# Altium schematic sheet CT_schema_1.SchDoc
size 391 x 258 mm
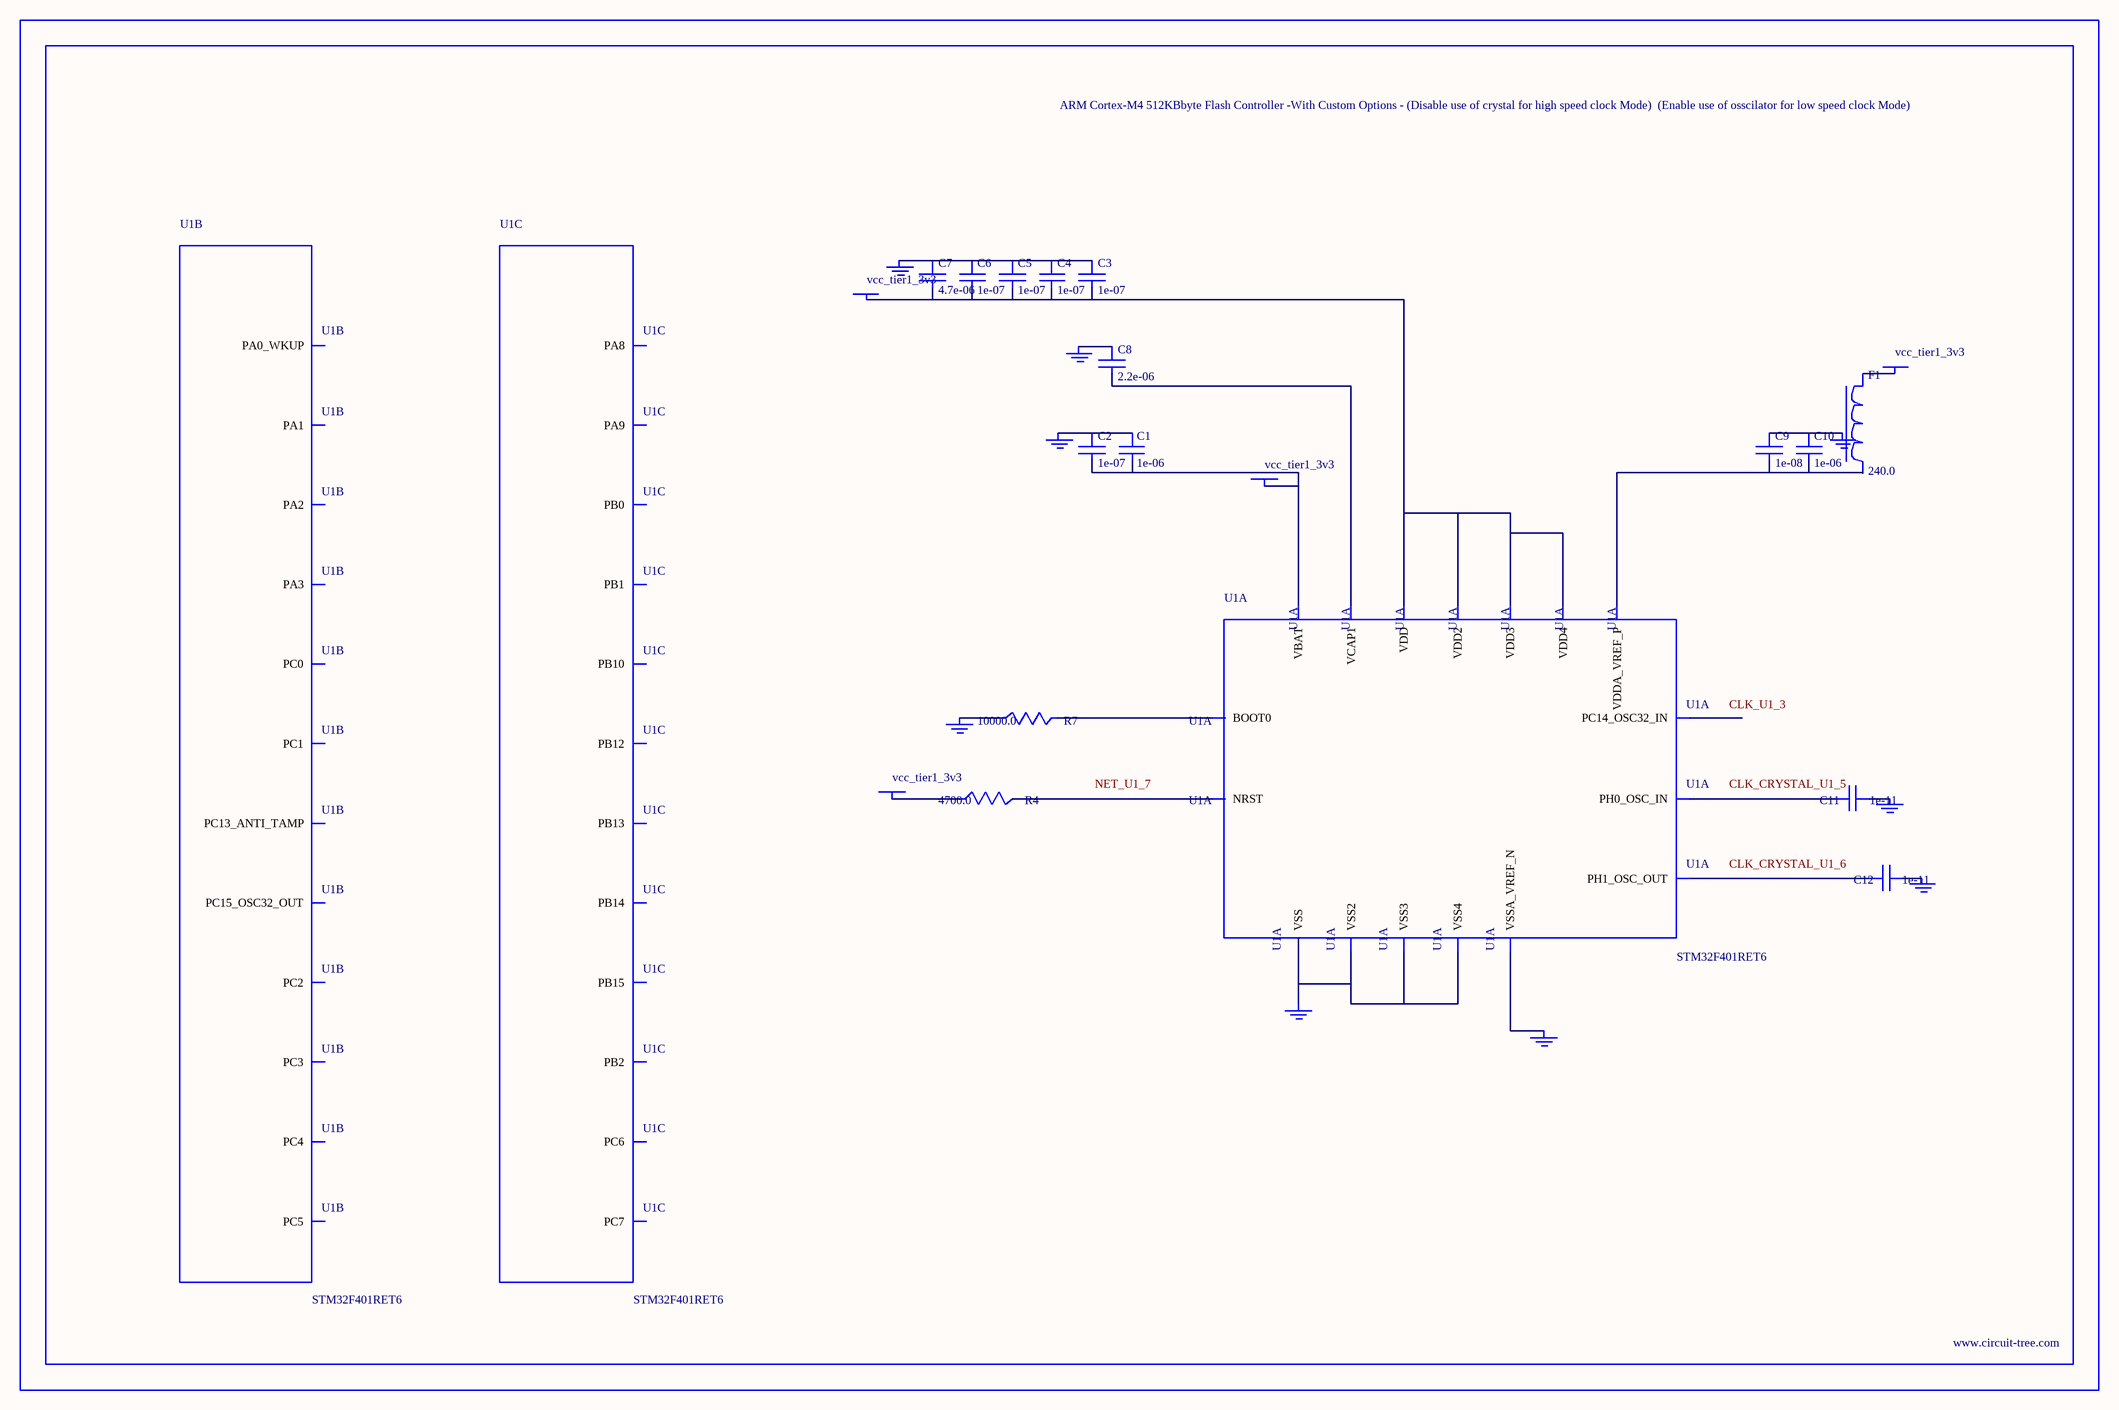
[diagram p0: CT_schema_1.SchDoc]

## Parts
BORDER0  (no value)
C1  1e-06  [C0603]
C2  1e-07  [C0603]
C3  1e-07  [C0603]
C4  1e-07  [C0603]
C5  1e-07  [C0603]
C6  1e-07  [C0603]
C7  4.7e-06  [C0603]
C8  2.2e-06  [C0603]
C9  1e-08  [C0603]
C10  1e-06  [C0603]
C11  1e-11  [C0402]
C12  1e-11  [C0402]
F1  240.0  [L0603]
GND_INSTANCE_0_0  (no value)
GND_INSTANCE_0_1  (no value)
GND_INSTANCE_0_2  (no value)
GND_INSTANCE_0_3  (no value)
GND_INSTANCE_0_4  (no value)
GND_INSTANCE_0_5  (no value)
GND_INSTANCE_0_6  (no value)
GND_INSTANCE_0_7  (no value)
GND_INSTANCE_0_8  (no value)
POWER_INSTANCE_0_0  vcc_tier1_3v3
POWER_INSTANCE_0_1  vcc_tier1_3v3
POWER_INSTANCE_0_2  vcc_tier1_3v3
POWER_INSTANCE_0_3  vcc_tier1_3v3
R4  4700.0  [R0603]
R7  10000.0  [R0603]
U1  STM32F401RET6  [LQFP64]  (parts A,B,C of 7)

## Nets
NetC1_1: C1.1 C2.1 GND_INSTANCE_0_0.0(GND)
NetC1_2: C1.2 C2.2 POWER_INSTANCE_0_0.0(PWR) U1.1(VBAT)
NetC3_1: C3.1 C4.1 C5.1 C6.1 C7.1 GND_INSTANCE_0_5.0(GND)
NetC3_2: C3.2 C4.2 C5.2 C6.2 C7.2 POWER_INSTANCE_0_2.0(PWR) U1.19(VDD) U1.32(VDD2) U1.48(VDD3) U1.64(VDD4)
NetC8_1: C8.1 GND_INSTANCE_0_6.0(GND)
NetC8_2: C8.2 U1.30(VCAP1)
NetC9_1: C9.1 C10.1 GND_INSTANCE_0_4.0(GND)
NetC9_2: C9.2 C10.2 U1.13(VDDA_VREF_P)
NetC11_1: C11.1 GND_INSTANCE_0_1.0(GND)
NetC11_2: C11.2 U1.5(PH0_OSC_IN)
NetC12_1: C12.1 GND_INSTANCE_0_2.0(GND)
NetC12_2: C12.2 U1.6(PH1_OSC_OUT)
NetF1_1: F1.1 POWER_INSTANCE_0_1.0(PWR)
NetGND_INSTANCE_0_3_0: GND_INSTANCE_0_3.0(GND) U1.12(VSSA_VREF_N)
NetGND_INSTANCE_0_7_0: GND_INSTANCE_0_7.0(GND) R7.1
NetGND_INSTANCE_0_8_0: GND_INSTANCE_0_8.0(GND) U1.18(VSS) U1.31(VSS2) U1.47(VSS3) U1.63(VSS4)
NetPOWER_INSTANCE_0_3_0: POWER_INSTANCE_0_3.0(PWR) R4.1
NetR4_2: R4.2 U1.7(NRST)
NetR7_2: R7.2 U1.60(BOOT0)

Not connected (* = marked no-connect by the designer): F1 2; U1 2(PC13_ANTI_TAMP) 3(PC14_OSC32_IN) 4(PC15_OSC32_OUT) 8(PC0) 9(PC1) 10(PC2) 11(PC3) 14(PA0_WKUP) 15(PA1) 16(PA2) 17(PA3) 24(PC4) 25(PC5) 26(PB0) 27(PB1) 28(PB2) 29(PB10) 33(PB12) 34(PB13) 35(PB14) 36(PB15) 37(PC6) 38(PC7) 41(PA8) 42(PA9)

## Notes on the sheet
- Labels drawn without touching a wire or pin: CLK_CRYSTAL_U1_5, CLK_CRYSTAL_U1_6, CLK_U1_3, NET_U1_7

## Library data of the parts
BORDER0 = BORDER_PAGE0
C1 C10 = C0603C105K3RACTU
C2-C6 = 06035C104K4Z2A
C7 = GRM188R6YA475KE15D
C8 = C0603C225K8RACTU
C9 = 06035C103K4Z2A
C11 C12 = C0402C100K3GACTU
F1 = Z0603C241ASMST
GND_INSTANCE_0_0-GND_INSTANCE_0_8 = GND
POWER_INSTANCE_0_0-POWER_INSTANCE_0_3 = PWR
R4 = RC0603JR-074K7L
R7 = RC0603JR-0710KL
